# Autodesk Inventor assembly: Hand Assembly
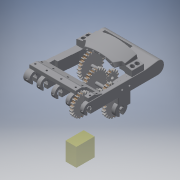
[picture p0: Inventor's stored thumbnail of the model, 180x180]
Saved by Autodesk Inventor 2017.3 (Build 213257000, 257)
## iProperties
Created: 2016-09
Part Number: Hand Assembly
Document SubType Name: Assembly
Designer: cmcdona
Author: cmcdona
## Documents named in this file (22)
- C:\Users\Tim_G\OneDrive - McMaster University\Documents\Documents\Books\McMaster First Year Courses\Winter Engineering 1C03\Project\Project Files (Prosthetic Frame Assembly)\Hand Assembly.iam
- C:\Users\Tim_G\OneDrive - McMaster University\Documents\Documents\Books\McMaster First Year Courses\Winter Engineering 1C03\Project\Project Files (Prosthetic Frame Assembly)\Hand - Frame.ipt
- C:\Users\Tim_G\OneDrive - McMaster University\Documents\Documents\Books\McMaster First Year Courses\Winter Engineering 1C03\Project\Project Files (Prosthetic Frame Assembly)\Hand - Digit 4.ipt
- C:\Users\Tim_G\OneDrive - McMaster University\Documents\Documents\Books\McMaster First Year Courses\Winter Engineering 1C03\Project\Project Files (Prosthetic Frame Assembly)\Hand - Digit 0-1.ipt
- C:\Users\Tim_G\OneDrive - McMaster University\Documents\Documents\Books\McMaster First Year Courses\Winter Engineering 1C03\Project\Project Files (Prosthetic Frame Assembly)\Hand - Distal Bridge.ipt
- C:\Users\Tim_G\OneDrive - McMaster University\Documents\Documents\Books\McMaster First Year Courses\Winter Engineering 1C03\Project\Project Files (Prosthetic Frame Assembly)\Hand - Digit 2-3.ipt
- C:\Users\Tim_G\OneDrive - McMaster University\Documents\Documents\Books\McMaster First Year Courses\Winter Engineering 1C03\Project\Project Files (Prosthetic Frame Assembly)\Hand - Proximal Bridge.ipt
- C:\Users\Tim_G\OneDrive - McMaster University\Documents\Documents\Books\McMaster First Year Courses\Winter Engineering 1C03\Project\Project Files (Prosthetic Frame Assembly)\Hand - Functional Workspace.ipt
- C:\Users\Tim_G\OneDrive - McMaster University\Documents\Documents\Books\McMaster First Year Courses\Winter Engineering 1C03\Project\Project Files (Prosthetic Frame Assembly)\Input Motor.ipt
- C:\Users\Tim_G\OneDrive - McMaster University\Documents\Documents\Books\McMaster First Year Courses\Winter Engineering 1C03\Project\Project Files (Prosthetic Frame Assembly)\Hand Assembly\Design Accelerator\Spur Gears1.iam
- C:\Users\Tim_G\OneDrive - McMaster University\Documents\Documents\Books\McMaster First Year Courses\Winter Engineering 1C03\Project\Project Files (Prosthetic Frame Assembly)\Hand Assembly\Design Accelerator\Spur Gear11.ipt
- C:\Users\Tim_G\OneDrive - McMaster University\Documents\Documents\Books\McMaster First Year Courses\Winter Engineering 1C03\Project\Project Files (Prosthetic Frame Assembly)\Hand Assembly\Design Accelerator\Spur Gear21.ipt
- C:\Users\Tim_G\OneDrive - McMaster University\Documents\Documents\Books\McMaster First Year Courses\Winter Engineering 1C03\Project\Project Files (Prosthetic Frame Assembly)\Hand Assembly\Design Accelerator\Spur Gears2.iam
- C:\Users\Tim_G\Desktop\1C03\Rod1.ipt
- C:\Users\Tim_G\OneDrive - McMaster University\Documents\Documents\Books\McMaster First Year Courses\Winter Engineering 1C03\Project\Project Files (Prosthetic Frame Assembly)\Hand Assembly\Design Accelerator\Spur Gears3.iam
- C:\Users\Tim_G\OneDrive - McMaster University\Documents\Documents\Books\McMaster First Year Courses\Winter Engineering 1C03\Project\Project Files (Prosthetic Frame Assembly)\Hand Assembly\Design Accelerator\Spur Gear13.ipt
- C:\Users\Tim_G\OneDrive - McMaster University\Documents\Documents\Books\McMaster First Year Courses\Winter Engineering 1C03\Project\Project Files (Prosthetic Frame Assembly)\Hand Assembly\Design Accelerator\Spur Gear23.ipt
- C:\Users\Tim_G\OneDrive - McMaster University\Documents\Documents\Books\McMaster First Year Courses\Winter Engineering 1C03\Project\Project Files (Prosthetic Frame Assembly)\Hand Assembly\Design Accelerator\Spur Gear12.ipt
- C:\Users\Tim_G\OneDrive - McMaster University\Documents\Documents\Books\McMaster First Year Courses\Winter Engineering 1C03\Project\Project Files (Prosthetic Frame Assembly)\Hand Assembly\Design Accelerator\Spur Gear22.ipt
- C:\Users\Tim_G\OneDrive - McMaster University\Documents\Documents\Books\McMaster First Year Courses\Winter Engineering 1C03\Project\Project Files (Prosthetic Frame Assembly)\Hand Assembly\Design Accelerator\Spur Gears5.iam
- C:\Users\Tim_G\OneDrive - McMaster University\Documents\Documents\Books\McMaster First Year Courses\Winter Engineering 1C03\Project\Project Files (Prosthetic Frame Assembly)\Hand Assembly\Design Accelerator\Spur Gears6.iam
- C:\Users\Tim_G\OneDrive - McMaster University\Documents\Documents\Books\McMaster First Year Courses\Winter Engineering 1C03\Project\Project Files (Prosthetic Frame Assembly)\Hand Assembly\Design Accelerator\Spur Gear16.ipt
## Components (27 placed, 12 different names)
1. Hand - Frame:1 — Flush:1, Flush:2, Mate:1, Mate:2, Flush:3, Mate:3, Mate:16, Mate:17, Mate:18, Mate:22, Mate:24, Mate:25
2. Hand - Digit 4:1 — Flush:1, Flush:2, Mate:1, Mate:4, Mate:5
3. Hand - Digit 0-1:1 — Mate:2, Flush:3, Mate:3, Mate:6, Mate:19, Mate:20, Mate:21, Mate:45, Mate:48, Mate:49, Mate:51
4. Hand - Distal Bridge:1 — Mate:4, Mate:5, Mate:6, Mate:7, Mate:8, Mate:9, Mate:10, Mate:11, Mate:12, Mate:13, Mate:14, Mate:15
5. Hand - Digit 2-3:1 — Mate:7, Mate:8, Mate:9
6. Hand - Digit 2-3:2 — Mate:10, Mate:11, Mate:12
7. Hand - Digit 2-3:3 — Mate:13, Mate:14, Mate:15
8. Hand - Proximal Bridge:1 — Mate:16, Mate:17, Mate:18
9. Hand - Functional Workspace:1 — Mate:19, Mate:20, Mate:21
10. Input Motor:1 — Mate:22, Mate:24, Mate:25, Mate:39, Mate:46, Flush:12
11. Spur Gears:1 [sub-assembly] — Mate:46, Flush:12
12. Spur Gear1:1 — Flush:4, Tangent:1, Mate:39
13. Spur Gear2:1 — Mate:26, Tangent:1, Mate:40
14. Spur Gears:2 [sub-assembly]
15. Spur Gear1:3 — Mate:34, Tangent:4, Flush:8
16. Spur Gear2:3 — Mate:35, Tangent:4, Flush:8
17. Rod1:1 — Mate:34, Mate:40
18. Rod1:2 — Mate:32, Mate:35, Mate:44, Mate:50
19. Spur Gears:3 [sub-assembly] — Mate:32
20. Spur Gear1:2 — Flush:5, Mate:44, Flush:11, Tangent:5, Tangent:6
21. Spur Gear2:2 — Flush:5, Mate:49, Mate:50, Tangent:7
22. Spur Gear2:4 — Mate:45, Flush:11, Tangent:5, Flush:13
23. Spur Gears:4 [sub-assembly]
24. Rod1:3 — Mate:48
25. Spur Gears:5 [sub-assembly]
26. Spur Gear1:4 — Tangent:6, Flush:13, Tangent:7
27. Rod1:4 — Mate:51
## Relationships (51: Mate 37, Flush 9, Tangent 5)
- Flush:1: Hand - Frame:1 ↔ Hand - Digit 4:1
- Flush:2: Hand - Frame:1 ↔ Hand - Digit 4:1
- Mate:1: Hand - Frame:1 ↔ Hand - Digit 4:1
- Mate:2: Hand - Frame:1 ↔ Hand - Digit 0-1:1
- Flush:3: Hand - Frame:1 ↔ Hand - Digit 0-1:1
- Mate:3: Hand - Frame:1 ↔ Hand - Digit 0-1:1
- Mate:4: Hand - Digit 4:1 ↔ Hand - Distal Bridge:1
- Mate:5: Hand - Digit 4:1 ↔ Hand - Distal Bridge:1
- Mate:6: Hand - Digit 0-1:1 ↔ Hand - Distal Bridge:1
- Mate:7: Hand - Distal Bridge:1 ↔ Hand - Digit 2-3:1
- Mate:8: Hand - Distal Bridge:1 ↔ Hand - Digit 2-3:1
- Mate:9: Hand - Distal Bridge:1 ↔ Hand - Digit 2-3:1
- Mate:10: Hand - Distal Bridge:1 ↔ Hand - Digit 2-3:2
- Mate:11: Hand - Distal Bridge:1 ↔ Hand - Digit 2-3:2
- Mate:12: Hand - Distal Bridge:1 ↔ Hand - Digit 2-3:2
- Mate:13: Hand - Distal Bridge:1 ↔ Hand - Digit 2-3:3
- Mate:14: Hand - Distal Bridge:1 ↔ Hand - Digit 2-3:3
- Mate:15: Hand - Distal Bridge:1 ↔ Hand - Digit 2-3:3
- Mate:16: Hand - Frame:1 ↔ Hand - Proximal Bridge:1
- Mate:17: Hand - Frame:1 ↔ Hand - Proximal Bridge:1
- Mate:18: Hand - Frame:1 ↔ Hand - Proximal Bridge:1
- Mate:19: Hand - Digit 0-1:1 ↔ Hand - Functional Workspace:1
- Mate:20: Hand - Digit 0-1:1 ↔ Hand - Functional Workspace:1
- Mate:21: Hand - Digit 0-1:1 ↔ Hand - Functional Workspace:1
- Mate:22: Hand - Frame:1 ↔ Input Motor:1
- Mate:24: Hand - Frame:1 ↔ Input Motor:1
- Mate:25: Hand - Frame:1 ↔ Input Motor:1
- Flush:4: Spur Gear1:1
- Mate:26: Spur Gear2:1
- Tangent:1: Spur Gear1:1 ↔ Spur Gear2:1
- Mate:32: Rod1:2 ↔ Spur Gears:3
- Mate:34: Spur Gear1:3 ↔ Rod1:1
- Mate:35: Spur Gear2:3 ↔ Rod1:2
- Flush:5: Spur Gear1:2 ↔ Spur Gear2:2
- Mate:39: Input Motor:1 ↔ Spur Gear1:1
- Tangent:4: Spur Gear1:3 ↔ Spur Gear2:3
- Flush:8: Spur Gear1:3 ↔ Spur Gear2:3
- Mate:40: Spur Gear2:1 ↔ Rod1:1
- Mate:44: Rod1:2 ↔ Spur Gear1:2
- Mate:45: Hand - Digit 0-1:1 ↔ Spur Gear2:4
- Flush:11: Spur Gear1:2 ↔ Spur Gear2:4
- Mate:46: Input Motor:1 ↔ Spur Gears:1
- Flush:12: Input Motor:1 ↔ Spur Gears:1
- Tangent:5: Spur Gear1:2 ↔ Spur Gear2:4
- Mate:48: Hand - Digit 0-1:1 ↔ Rod1:3
- Mate:49: Hand - Digit 0-1:1 ↔ Spur Gear2:2
- Mate:50: Rod1:2 ↔ Spur Gear2:2
- Tangent:6: Spur Gear1:2 ↔ Spur Gear1:4
- Flush:13: Spur Gear2:4 ↔ Spur Gear1:4
- Tangent:7: Spur Gear2:2 ↔ Spur Gear1:4
- Mate:51: Hand - Digit 0-1:1 ↔ Rod1:4
